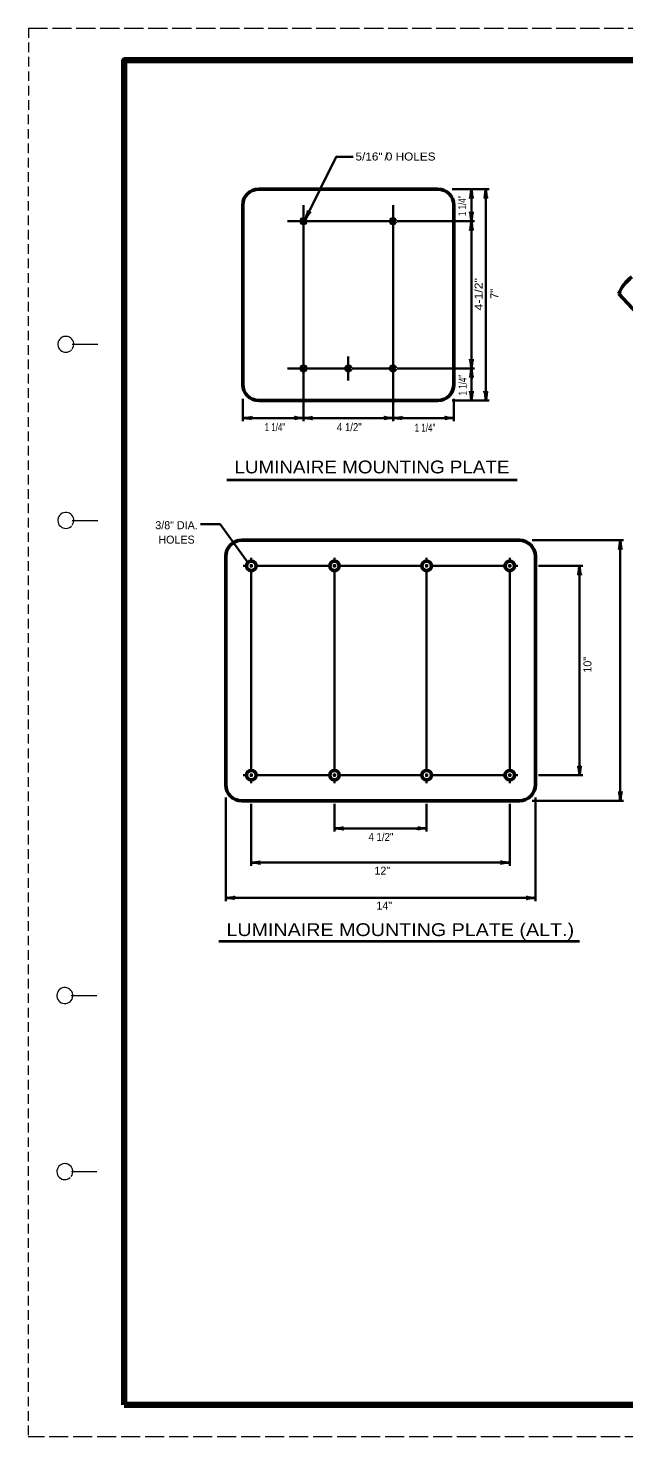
# Model space of a CAD drawing. Extents: x -67 to 613, y -55 to 385.
# Drawn here: x -67 to 119.2, y -55.5 to 384.6 of the extents above; entities that cross this region are included whole.
import ezdxf
from ezdxf.enums import TextEntityAlignment as Align

# ---------------------------------------------------------------- set-up
doc = ezdxf.new("R2010")
doc.units = 0
doc.linetypes.add('LONG_DASHED', pattern=[7.5, 6, -1.5])
doc.linetypes.add('MEDIUM_DASHED', pattern=[4.5, 3, -1.5])
doc.layers.add('1', color=7, linetype='Continuous', lineweight=13)
doc.layers.add('61', color=7, linetype='Continuous', lineweight=35)

msp = doc.modelspace()

# ---------------------------------------------------------------- linework, layer by layer
at = {"layer": '1', "linetype": 'MEDIUM_DASHED'}
msp.add_line((-66.959, 384.56), (-67.019, -55.48), dxfattribs=at)
at = {"layer": '1', "lineweight": 53}
for p, q in [((5.052, 334.27), (61.052, 334.27)), ((0.052, 273.27), (0.052, 329.27)), ((66.052, 329.27), (66.052, 273.27)), ((131.907, 286.229), (117.606, 301.565)), ((61.052, 268.27), (5.052, 268.27)), ((-0.255, 224.583), (86.543, 224.583)), ((-5.255, 148.221), (-5.255, 219.583)), ((91.543, 219.583), (91.543, 148.221)), ((86.543, 143.221), (-0.255, 143.221))]:
    msp.add_line(p, q, dxfattribs=at)
at = {"layer": '1', "lineweight": 35}
for p, q in [((65.552, 334.27), (77.052, 334.27)), ((71.552, 324.27), (71.552, 334.27)), ((76.052, 334.27), (76.052, 268.27)), ((19.052, 325.52), (19.052, 329.27)), ((47.052, 329.27), (47.052, 325.52)), ((14.052, 324.27), (17.802, 324.27)), ((18.802, 324.27), (19.302, 324.27)), ((19.052, 324.02), (19.052, 324.52)), ((19.052, 279.52), (19.052, 323.02)), ((20.302, 324.27), (45.802, 324.27)), ((46.802, 324.27), (47.302, 324.27)), ((47.052, 324.52), (47.052, 324.02)), ((47.052, 323.02), (47.052, 279.52)), ((48.302, 324.27), (72.552, 324.27)), ((71.552, 324.27), (71.552, 278.27)), ((33.052, 282.02), (33.052, 279.52)), ((17.802, 278.27), (14.052, 278.27)), ((19.302, 278.27), (18.802, 278.27)), ((19.052, 278.02), (19.052, 278.52)), ((31.802, 278.27), (20.302, 278.27)), ((33.302, 278.27), (32.802, 278.27)), ((33.052, 278.52), (33.052, 278.02)), ((45.802, 278.27), (34.302, 278.27)), ((47.302, 278.27), (46.802, 278.27)), ((47.052, 278.52), (47.052, 278.02)), ((72.552, 278.27), (48.302, 278.27)), ((71.552, 278.27), (71.552, 268.27)), ((19.052, 261.77), (19.052, 277.02)), ((33.052, 277.02), (33.052, 274.52)), ((47.052, 277.02), (47.052, 261.77)), ((0.052, 268.77), (0.052, 261.77)), ((66.052, 268.77), (66.052, 261.77)), ((65.552, 268.27), (77.052, 268.27)), ((19.052, 262.77), (0.052, 262.77)), ((-7.042, 229.638), (-13.126, 229.638)), ((1.684, 217.643), (-7.042, 229.638)), ((90.543, 224.583), (119.085, 224.583)), ((118.085, 224.583), (118.085, 143.221)), ((1.745, 216.583), (0.245, 216.583)), ((2.245, 216.583), (3.245, 216.583)), ((2.745, 217.583), (2.745, 219.083)), ((2.745, 216.083), (2.745, 217.083)), ((3.745, 216.583), (27.745, 216.583)), ((28.245, 216.583), (29.245, 216.583)), ((28.745, 217.583), (28.745, 219.083)), ((28.745, 217.083), (28.745, 216.083)), ((29.745, 216.583), (56.543, 216.583)), ((57.043, 216.583), (58.043, 216.583)), ((57.543, 217.583), (57.543, 219.083)), ((57.543, 217.083), (57.543, 216.083)), ((58.543, 216.583), (82.543, 216.583)), ((83.043, 216.583), (84.043, 216.583)), ((83.543, 217.583), (83.543, 219.083)), ((83.543, 217.083), (83.543, 216.083)), ((84.543, 216.583), (86.043, 216.583)), ((92.543, 216.583), (106.344, 216.583)), ((105.344, 216.583), (105.344, 151.221)), ((2.745, 152.221), (2.745, 215.583)), ((28.745, 215.583), (28.745, 152.221)), ((57.543, 215.583), (57.543, 152.221)), ((83.543, 215.583), (83.543, 152.221)), ((1.745, 151.221), (0.245, 151.221)), ((3.245, 151.221), (2.245, 151.221)), ((2.745, 150.721), (2.745, 151.721)), ((2.745, 150.221), (2.745, 148.721)), ((27.745, 151.221), (3.745, 151.221)), ((29.245, 151.221), (28.245, 151.221)), ((28.745, 151.721), (28.745, 150.721)), ((28.745, 150.221), (28.745, 148.721)), ((56.543, 151.221), (29.745, 151.221)), ((58.043, 151.221), (57.043, 151.221)), ((57.543, 151.721), (57.543, 150.721)), ((57.543, 150.221), (57.543, 148.721)), ((82.543, 151.221), (58.543, 151.221)), ((84.043, 151.221), (83.043, 151.221)), ((83.543, 151.721), (83.543, 150.721)), ((83.543, 150.221), (83.543, 148.721)), ((84.543, 151.221), (86.043, 151.221)), ((92.543, 151.221), (106.344, 151.221)), ((-5.255, 144.221), (-5.255, 111.869)), ((2.745, 142.221), (2.745, 122.9)), ((28.745, 142.221), (28.745, 133.588)), ((57.543, 142.221), (57.543, 133.588)), ((83.543, 142.221), (83.543, 122.9)), ((90.543, 143.221), (119.085, 143.221)), ((91.543, 144.221), (91.543, 111.869)), ((28.745, 134.588), (57.543, 134.588)), ((2.745, 123.9), (83.543, 123.9)), ((-5.255, 112.869), (91.543, 112.869))]:
    msp.add_line(p, q, dxfattribs=at)
at = {"layer": '1', "lineweight": 40}
for p, q in [((-4.929, 243.433), (85.864, 243.433)), ((-7.429, 99.306), (105.358, 99.306))]:
    msp.add_line(p, q, dxfattribs=at)
at = {"layer": '1', "lineweight": 35}
for points in [[(19.582, 324.8), (29.235, 344.332), (34.544, 344.332)], [(19.052, 262.77), (47.052, 262.77), (66.052, 262.77)]]:
    msp.add_lwpolyline(points, dxfattribs=at)
at = {"layer": '1', "lineweight": 53}
for centre, radius in [((19.052, 324.27), 0.75), ((47.052, 324.27), 0.75), ((19.052, 278.27), 0.75), ((33.052, 278.27), 0.75), ((47.052, 278.27), 0.75), ((2.745, 216.583), 1.5), ((28.745, 216.583), 1.5), ((57.543, 216.583), 1.5), ((83.543, 216.583), 1.5), ((2.745, 151.221), 1.5), ((28.745, 151.221), 1.5), ((57.543, 151.221), 1.5), ((83.543, 151.221), 1.5)]:
    msp.add_circle(centre, radius, dxfattribs=at)
for centre, radius, start, end in [((5.052, 329.27), 5, 90, 180), ((61.052, 329.27), 5, 0, 90), ((128.914, 297.056), 12.174, 126.36545, 158.25906), ((5.052, 273.27), 5, 180, 270), ((61.052, 273.27), 5, 270, 0), ((-0.255, 219.583), 5, 90, 180), ((86.543, 219.583), 5, 0, 90), ((-0.255, 148.221), 5, 180, 270), ((86.543, 148.221), 5, 270, 0)]:
    msp.add_arc(centre, radius, start, end, dxfattribs=at)
at = {"layer": '1', "lineweight": 40}
for centre, major_axis, ratio, start_param, end_param in [((71.34, 333.149), (0.176, 1.756), 0.07063, 3.1407148, 5.41811), ((71.34, 333.149), (0.176, 1.756), 0.07063, 3.1407148, 5.41811), ((71.828, 333.179), (-0.156, 1.786), 0.122415, 0.8963533, 3.1415927), ((71.828, 333.179), (-0.156, 1.786), 0.122415, 0.8963533, 3.1415927), ((75.84, 333.149), (0.176, 1.756), 0.07063, 3.1407148, 5.41811), ((75.84, 333.149), (0.176, 1.756), 0.07063, 3.1407148, 5.41811), ((76.328, 333.179), (-0.156, 1.786), 0.122415, 0.8963533, 3.1415927), ((76.328, 333.179), (-0.156, 1.786), 0.122415, 0.8963533, 3.1415927), ((19.818, 325.901), (-0.651, -1.67), 0.122415, 0.8963533, 3.1415927), ((20.268, 325.711), (0.936, 1.497), 0.07063, 6.2823074, 8.5597026), ((71.276, 325.361), (0.156, -1.786), 0.122415, 0.8963533, 3.1415927), ((71.276, 325.361), (0.156, -1.786), 0.122415, 0.8963533, 3.1415927), ((71.763, 325.39), (-0.176, -1.756), 0.07063, 3.1407148, 5.41811), ((71.763, 325.39), (-0.176, -1.756), 0.07063, 3.1407148, 5.41811), ((71.34, 323.149), (0.176, 1.756), 0.07063, 3.1407148, 5.41811), ((71.34, 323.149), (0.176, 1.756), 0.07063, 3.1407148, 5.41811), ((71.828, 323.179), (-0.156, 1.786), 0.122415, 0.8963533, 3.1415927), ((71.828, 323.179), (-0.156, 1.786), 0.122415, 0.8963533, 3.1415927), ((71.276, 279.361), (0.156, -1.786), 0.122415, 0.8963533, 3.1415927), ((71.276, 279.361), (0.156, -1.786), 0.122415, 0.8963533, 3.1415927), ((71.34, 277.149), (0.176, 1.756), 0.07063, 3.1407148, 5.41811), ((71.34, 277.149), (0.176, 1.756), 0.07063, 3.1407148, 5.41811), ((71.828, 277.179), (-0.156, 1.786), 0.122415, 0.8963533, 3.1415927), ((71.828, 277.179), (-0.156, 1.786), 0.122415, 0.8963533, 3.1415927), ((71.763, 279.39), (-0.176, -1.756), 0.07063, 3.1407148, 5.41811), ((71.763, 279.39), (-0.176, -1.756), 0.07063, 3.1407148, 5.41811), ((71.276, 269.361), (0.156, -1.786), 0.122415, 0.8963533, 3.1415927), ((71.276, 269.361), (0.156, -1.786), 0.122415, 0.8963533, 3.1415927), ((71.763, 269.39), (-0.176, -1.756), 0.07063, 3.1407148, 5.41811), ((71.763, 269.39), (-0.176, -1.756), 0.07063, 3.1407148, 5.41811), ((75.776, 269.361), (0.156, -1.786), 0.122415, 0.8963533, 3.1415927), ((75.776, 269.361), (0.156, -1.786), 0.122415, 0.8963533, 3.1415927), ((76.263, 269.39), (-0.176, -1.756), 0.07063, 3.1407148, 5.41811), ((76.263, 269.39), (-0.176, -1.756), 0.07063, 3.1407148, 5.41811), ((1.172, 262.558), (-1.756, 0.176), 0.07063, 3.1407148, 5.41811), ((1.143, 263.046), (-1.786, -0.156), 0.122415, 0.8963533, 3.1415927), ((17.961, 262.494), (1.786, 0.156), 0.122415, 0.8963533, 3.1415927), ((17.961, 262.494), (1.786, 0.156), 0.122415, 0.8963533, 3.1415927), ((17.931, 262.981), (1.756, -0.176), 0.07063, 3.1407148, 5.41811), ((17.931, 262.981), (1.756, -0.176), 0.07063, 3.1407148, 5.41811), ((20.172, 262.558), (-1.756, 0.176), 0.07063, 3.1407148, 5.41811), ((20.172, 262.558), (-1.756, 0.176), 0.07063, 3.1407148, 5.41811), ((20.143, 263.046), (-1.786, -0.156), 0.122415, 0.8963533, 3.1415927), ((20.143, 263.046), (-1.786, -0.156), 0.122415, 0.8963533, 3.1415927), ((45.961, 262.494), (1.786, 0.156), 0.122415, 0.8963533, 3.1415927), ((45.961, 262.494), (1.786, 0.156), 0.122415, 0.8963533, 3.1415927), ((45.931, 262.981), (1.756, -0.176), 0.07063, 3.1407148, 5.41811), ((45.931, 262.981), (1.756, -0.176), 0.07063, 3.1407148, 5.41811), ((48.172, 262.558), (-1.756, 0.176), 0.07063, 3.1407148, 5.41811), ((48.172, 262.558), (-1.756, 0.176), 0.07063, 3.1407148, 5.41811), ((48.143, 263.046), (-1.786, -0.156), 0.122415, 0.8963533, 3.1415927), ((48.143, 263.046), (-1.786, -0.156), 0.122415, 0.8963533, 3.1415927), ((64.961, 262.494), (1.786, 0.156), 0.122415, 0.8963533, 3.1415927), ((64.961, 262.494), (1.786, 0.156), 0.122415, 0.8963533, 3.1415927), ((64.931, 262.981), (1.756, -0.176), 0.07063, 3.1407148, 5.41811), ((64.931, 262.981), (1.756, -0.176), 0.07063, 3.1407148, 5.41811), ((117.873, 223.462), (0.176, 1.756), 0.07063, 3.1407148, 5.41811), ((117.873, 223.462), (0.176, 1.756), 0.07063, 3.1407148, 5.41811), ((118.361, 223.491), (-0.156, 1.786), 0.122415, 0.8963533, 3.1415927), ((118.361, 223.491), (-0.156, 1.786), 0.122415, 0.8963533, 3.1415927), ((105.132, 215.462), (0.176, 1.756), 0.07063, 3.1407148, 5.41811), ((105.132, 215.462), (0.176, 1.756), 0.07063, 3.1407148, 5.41811), ((105.62, 215.491), (-0.156, 1.786), 0.122415, 0.8963533, 3.1415927), ((105.62, 215.491), (-0.156, 1.786), 0.122415, 0.8963533, 3.1415927), ((105.068, 152.312), (0.156, -1.786), 0.122415, 0.8963533, 3.1415927), ((105.068, 152.312), (0.156, -1.786), 0.122415, 0.8963533, 3.1415927), ((105.556, 152.341), (-0.176, -1.756), 0.07063, 3.1407148, 5.41811), ((105.556, 152.341), (-0.176, -1.756), 0.07063, 3.1407148, 5.41811), ((117.808, 144.312), (0.156, -1.786), 0.122415, 0.8963533, 3.1415927), ((117.808, 144.312), (0.156, -1.786), 0.122415, 0.8963533, 3.1415927), ((118.296, 144.341), (-0.176, -1.756), 0.07063, 3.1407148, 5.41811), ((118.296, 144.341), (-0.176, -1.756), 0.07063, 3.1407148, 5.41811), ((29.865, 134.376), (-1.756, 0.176), 0.07063, 3.1407148, 5.41811), ((29.865, 134.376), (-1.756, 0.176), 0.07063, 3.1407148, 5.41811), ((29.836, 134.864), (-1.786, -0.156), 0.122415, 0.8963533, 3.1415927), ((29.836, 134.864), (-1.786, -0.156), 0.122415, 0.8963533, 3.1415927), ((56.452, 134.312), (1.786, 0.156), 0.122415, 0.8963533, 3.1415927), ((56.452, 134.312), (1.786, 0.156), 0.122415, 0.8963533, 3.1415927), ((56.422, 134.8), (1.756, -0.176), 0.07063, 3.1407148, 5.41811), ((56.422, 134.8), (1.756, -0.176), 0.07063, 3.1407148, 5.41811), ((3.865, 123.688), (-1.756, 0.176), 0.07063, 3.1407148, 5.41811), ((3.865, 123.688), (-1.756, 0.176), 0.07063, 3.1407148, 5.41811), ((3.836, 124.176), (-1.786, -0.156), 0.122415, 0.8963533, 3.1415927), ((3.836, 124.176), (-1.786, -0.156), 0.122415, 0.8963533, 3.1415927), ((82.452, 123.623), (1.786, 0.156), 0.122415, 0.8963533, 3.1415927), ((82.452, 123.623), (1.786, 0.156), 0.122415, 0.8963533, 3.1415927), ((82.422, 124.111), (1.756, -0.176), 0.07063, 3.1407148, 5.41811), ((82.422, 124.111), (1.756, -0.176), 0.07063, 3.1407148, 5.41811), ((-4.135, 112.657), (-1.756, 0.176), 0.07063, 3.1407148, 5.41811), ((-4.135, 112.657), (-1.756, 0.176), 0.07063, 3.1407148, 5.41811), ((-4.135, 112.657), (-1.756, 0.176), 0.07063, 3.1407148, 5.41811), ((-4.164, 113.145), (-1.786, -0.156), 0.122415, 0.8963533, 3.1415927), ((-4.164, 113.145), (-1.786, -0.156), 0.122415, 0.8963533, 3.1415927), ((-4.164, 113.145), (-1.786, -0.156), 0.122415, 0.8963533, 3.1415927), ((90.452, 112.593), (1.786, 0.156), 0.122415, 0.8963533, 3.1415927), ((90.452, 112.593), (1.786, 0.156), 0.122415, 0.8963533, 3.1415927), ((90.422, 113.08), (1.756, -0.176), 0.07063, 3.1407148, 5.41811), ((90.422, 113.08), (1.756, -0.176), 0.07063, 3.1407148, 5.41811)]:
    msp.add_ellipse(centre, major_axis=major_axis, ratio=ratio, start_param=start_param, end_param=end_param, dxfattribs=at)
at = {"layer": '61', "linetype": 'LONG_DASHED', "lineweight": 13}
for p, q in [((-66.959, 384.56), (613.061, 384.56)), ((613.041, -55.46), (-67.019, -55.48))]:
    msp.add_line(p, q, dxfattribs=at)
at = {"layer": '61', "lineweight": 13}
for p, q in [((-53.239, 285.8), (-45.259, 285.82)), ((-53.259, 230.8), (-45.259, 230.8)), ((-53.539, 82.38), (-45.539, 82.38)), ((-53.519, 27.36), (-45.539, 27.36))]:
    msp.add_line(p, q, dxfattribs=at)
at = {"layer": '61', "lineweight": 158}
msp.add_line((602.101, -45.48), (-36.959, -45.46), dxfattribs=at)
msp.add_lwpolyline([(602.081, 374.56), (-36.959, 374.56), (-36.959, -45.46)], dxfattribs=at)
at = {"layer": '61', "lineweight": 13}
for centre, start, end in [((-55.261, 285.801), 323.13009, 316.23216), ((-55.261, 230.801), 323.13009, 315.37577), ((-55.541, 82.361), 322.67175, 321.71615), ((-55.541, 27.361), 323.13009, 312.31439)]:
    msp.add_arc(centre, 2.5, start, end, dxfattribs=at)

# ---------------------------------------------------------------- texts
at = {"layer": '1'}
for s, height, width, p in [('5/16" 0 HOLES', 2.5, 1.1, (35.314, 343.219)), ('1 1/4"', 2.5, 0.75, (6.887, 258.679)), ('4 1/2"', 2.5, 0.9, (29.492, 258.679)), ('1 1/4"', 2.5, 0.75, (53.809, 258.508)), ('LUMINAIRE MOUNTING PLATE', 4, 1.1, (-2.532, 245.489)), ('4 1/2"', 2.5, 0.9, (39.381, 130.665)), ('LUMINAIRE MOUNTING PLATE (ALT.)', 4, 1.15, (-5.032, 100.95))]:
    msp.add_text(s, height=height, dxfattribs=dict(at, width=width)).set_placement(p)
for s, p in [('/', (44.391, 343.219)), ('12"', (41.237, 120.146)), ('14"', (41.855, 109.215))]:
    msp.add_text(s, height=2.5, dxfattribs=at).set_placement(p)
for s, width, p in [('1 1/4"', 0.75, (69.907, 325.831)), ('4-1/2"', 1.15, (75.044, 296.367)), ('7"', 1.05, (80.011, 299.964)), ('1 1/4"', 0.75, (70.078, 269.814))]:
    msp.add_text(s, height=2.5, rotation=90, dxfattribs=dict(at, width=width)).set_placement(p)
for s, p in [('3/8" DIA.', (-20.635, 228.043)), ('HOLES', (-20.635, 223.543))]:
    msp.add_text(s, height=2.5, dxfattribs=at).set_placement(p, align=Align.CENTER)
msp.add_text('10"', height=2.5, rotation=90, dxfattribs=at).set_placement((109.069, 183.258))

doc.saveas('drawing.dxf')
